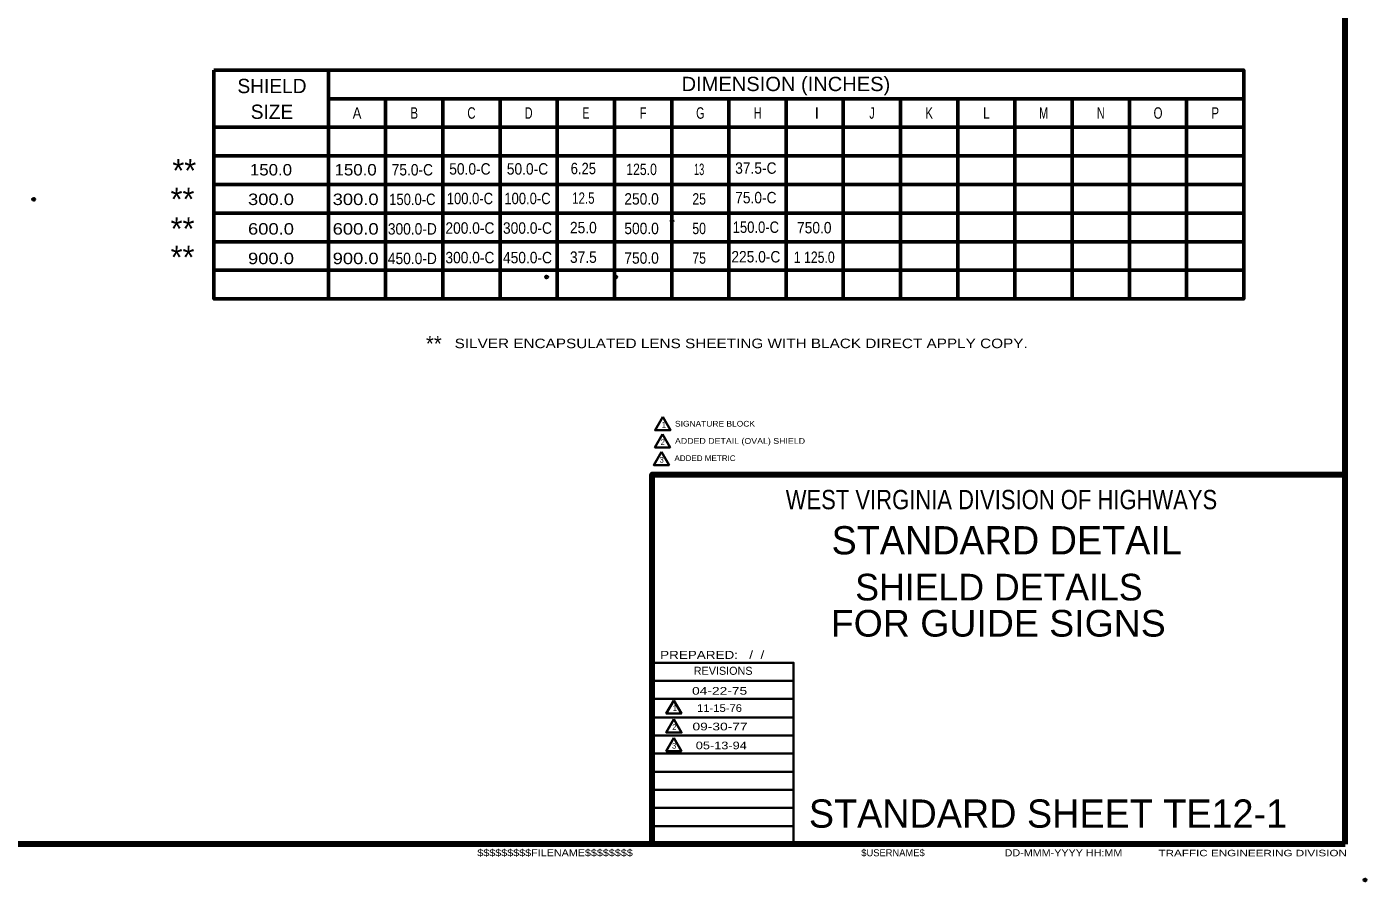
# Model space of a CAD drawing. Extents: x -96 to 760, y -448 to 96.
# Drawn here: x 338.4 to 759.8, y -448.1 to -179.2 of the extents above; entities that cross this region are included whole.
import ezdxf
from ezdxf.enums import TextEntityAlignment as Align

# ---------------------------------------------------------------- set-up
doc = ezdxf.new("R2010")
doc.units = 0
doc.header["$LTSCALE"] = 1.4
doc.header["$PDMODE"] = 32
doc.header["$PDSIZE"] = 0.7
doc.layers.add('1', color=7, linetype='Continuous', lineweight=40)
doc.layers.add('61', color=7, linetype='Continuous', lineweight=35)

msp = doc.modelspace()

# ---------------------------------------------------------------- linework, layer by layer
at = {"layer": '1', "lineweight": 158}
for q in [(753.127, 89.656), (753.127, -320.144), (-38.473, -436.444)]:
    msp.add_line((753.127, -436.444), q, dxfattribs=at)
at = {"layer": '1', "lineweight": 13}
msp.add_line((753.127, -436.444), (753.127, 89.656), dxfattribs=at)
at = {"layer": '1', "lineweight": 53}
for p, q in [((433.269, -264.853), (433.269, -192.853)), ((433.269, -201.853), (721.269, -201.853)), ((451.269, -264.853), (451.269, -201.853)), ((469.269, -264.853), (469.269, -201.853)), ((487.269, -264.853), (487.269, -201.853)), ((505.269, -264.853), (505.269, -201.853)), ((523.269, -264.853), (523.269, -201.853)), ((541.269, -264.853), (541.269, -201.853)), ((559.269, -264.853), (559.269, -201.853)), ((577.269, -264.853), (577.269, -201.853)), ((595.269, -264.853), (595.269, -201.853)), ((613.269, -264.853), (613.269, -201.853)), ((631.269, -264.853), (631.269, -201.853)), ((649.269, -264.853), (649.269, -201.853)), ((667.269, -264.853), (667.269, -201.853)), ((685.269, -264.853), (685.269, -201.853)), ((703.269, -264.853), (703.269, -201.853)), ((577.269, -210.853), (595.269, -210.853)), ((590.769, -210.853), (617.769, -210.853)), ((397.269, -219.853), (721.269, -219.853)), ((397.269, -228.853), (721.269, -228.853)), ((397.269, -237.854), (721.269, -237.854)), ((397.269, -246.854), (721.269, -246.854)), ((397.269, -255.854), (721.269, -255.854))]:
    msp.add_line(p, q, dxfattribs=at)
at = {"layer": '1', "lineweight": 35}
for p, q in [((579.627, -385.044), (535.127, -385.044)), ((579.627, -390.744), (535.127, -390.744)), ((579.627, -396.544), (535.127, -396.544)), ((579.627, -402.244), (535.127, -402.244)), ((579.627, -407.944), (535.127, -407.944)), ((579.627, -413.644), (535.127, -413.644)), ((579.627, -419.344), (535.127, -419.344)), ((579.627, -425.044), (535.127, -425.044)), ((579.627, -430.744), (535.127, -430.744))]:
    msp.add_line(p, q, dxfattribs=at)
at = {"layer": '1', "lineweight": 53}
msp.add_lwpolyline([(397.269, -192.853), (721.269, -192.853), (721.269, -264.853), (397.269, -264.853)], close=True, dxfattribs=at)
for points in [[(397.269, -210.853), (433.269, -210.853), (451.269, -210.853), (469.269, -210.853), (487.269, -210.853), (505.269, -210.853), (523.269, -210.853), (541.269, -210.853), (559.269, -210.853), (581.769, -210.853)], [(613.269, -210.853), (631.269, -210.853), (649.269, -210.853), (667.269, -210.853), (685.269, -210.853), (703.269, -210.853), (721.269, -210.853)]]:
    msp.add_lwpolyline(points, dxfattribs=at)
at = {"layer": '1', "lineweight": 35}
for points in [[(538.465, -302.008), (536.065, -306.165), (540.865, -306.165)], [(538.375, -307.418), (535.976, -311.575), (540.776, -311.575)], [(538.037, -313.012), (535.637, -317.169), (540.437, -317.169)], [(541.94, -391.203), (539.539, -395.359), (544.34, -395.359)], [(541.983, -397.144), (539.583, -401.3), (544.383, -401.3)], [(541.943, -402.987), (539.543, -407.144), (544.343, -407.144)]]:
    msp.add_lwpolyline(points, close=True, dxfattribs=at)
at = {"layer": '1', "lineweight": 158}
msp.add_lwpolyline([(535.127, -436.444), (535.127, -320.144), (753.127, -320.144)], dxfattribs=at)
at = {"layer": '1', "lineweight": 35}
msp.add_lwpolyline([(579.627, -436.444), (579.627, -379.344), (535.127, -379.344)], dxfattribs=at)
at = {"layer": '1'}
for p in [(340.552, -233.54), (541.41, -240.277), (501.934, -257.972), (523.715, -257.972), (759.427, -447.744)]:
    msp.add_point(p, dxfattribs=at)
at = {"layer": '61', "lineweight": 53}
for q in [(600.427, -436.444), (600.427, -436.444), (600.427, -436.444), (600.727, -436.444), (600.727, -436.444)]:
    msp.add_line((753.127, -436.444), q, dxfattribs=at)

# ---------------------------------------------------------------- texts
at = {"layer": '1'}
for s, height, p in [('SHIELD', 4.5, (415.526, -200.103)), ('SIZE', 4.5, (415.526, -208.203)), ('I', 3.6, (586.931, -208.154)), ('**', 7.2, (387.929, -228.069)), ('**', 7.2, (387.379, -237.064)), ('**', 7.2, (387.379, -246.365)), ('**', 7.2, (387.379, -255.334)), ('**', 4.8, (466.44, -281.338)), ('STANDARD DETAIL', 8.881, (646.677, -345.244)), ('SHIELD DETAILS', 8.391, (644.222, -359.745))]:
    msp.add_text(s, height=height, dxfattribs=at).set_placement(p, align=Align.CENTER)
for s, height, width, p in [('DIMENSION (INCHES)', 4.5, 1.05, (577.215, -199.456)), ('A', 3.6, 0.85, (442.283, -208.154)), ('B', 3.6, 0.75, (460.283, -208.154)), ('C', 3.6, 0.75, (478.283, -208.154)), ('D', 3.6, 0.7, (496.283, -208.154)), ('E', 3.6, 0.7, (514.283, -208.154)), ('F', 3.6, 0.75, (532.283, -208.154)), ('G', 3.6, 0.7, (550.283, -208.154)), ('H', 3.6, 0.7, (568.283, -208.154)), ('J', 3.6, 0.7, (604.283, -208.154)), ('K', 3.6, 0.75, (622.283, -208.154)), ('L', 3.6, 0.75, (640.283, -208.154)), ('M', 3.6, 0.7, (658.283, -208.154)), ('N', 3.6, 0.7, (676.283, -208.154)), ('O', 3.6, 0.75, (694.283, -208.154)), ('P', 3.6, 0.75, (712.283, -208.154)), ('150.0', 3.6, 1.1, (415.206, -226.014)), ('150.0', 3.6, 1.1, (441.839, -226.014)), ('75.0-C', 3.6, 0.9, (459.683, -226.014)), ('50.0-C', 3.6, 0.9, (477.794, -225.747)), ('50.0-C', 3.6, 0.9, (495.905, -225.747)), ('6.25', 3.6, 0.85, (513.483, -225.614)), ('125.0', 3.6, 0.8, (531.802, -225.879)), ('13', 3.6, 0.6, (549.913, -225.879)), ('37.5-C', 3.6, 0.9, (567.757, -225.48)), ('300.0', 3.6, 1.2, (415.206, -235.314)), ('300.0', 3.6, 1.2, (441.839, -235.314)), ('150.0-C', 3.6, 0.85, (459.683, -235.314)), ('100.0-C', 3.6, 0.85, (477.794, -235.047)), ('100.0-C', 3.6, 0.85, (495.905, -235.047)), ('12.5', 3.6, 0.75, (513.483, -234.914)), ('250.0', 3.6, 0.9, (531.802, -235.179)), ('25', 3.6, 0.8, (549.913, -235.179)), ('75.0-C', 3.6, 0.9, (567.757, -234.78)), ('600.0', 3.6, 1.2, (415.206, -244.614)), ('600.0', 3.6, 1.2, (441.839, -244.614)), ('300.0-D', 3.6, 0.9, (459.683, -244.614)), ('200.0-C', 3.6, 0.9, (477.794, -244.347)), ('300.0-C', 3.6, 0.9, (495.905, -244.347)), ('25.0', 3.6, 0.9, (513.483, -244.214)), ('500.0', 3.6, 0.9, (531.802, -244.479)), ('50', 3.6, 0.8, (549.913, -244.479)), ('150.0-C', 3.6, 0.85, (567.757, -244.08)), ('750.0', 3.6, 0.9, (586.134, -244.237)), ('900.0', 3.6, 1.2, (415.206, -253.914)), ('900.0', 3.6, 1.2, (441.839, -253.914)), ('450.0-D', 3.6, 0.9, (459.683, -253.914)), ('300.0-C', 3.6, 0.9, (477.794, -253.647)), ('450.0-C', 3.6, 0.9, (495.905, -253.647)), ('37.5', 3.6, 0.9, (513.483, -253.514)), ('750.0', 3.6, 0.9, (531.802, -253.779)), ('75', 3.6, 0.8, (549.913, -253.779)), ('225.0-C', 3.6, 0.9, (567.757, -253.38)), ('1 125.0', 3.6, 0.8, (586.134, -253.537)), ('WEST VIRGINIA DIVISION OF HIGHWAYS', 6.089, 0.85, (645.027, -331.044)), ('FOR GUIDE SIGNS', 8.391, 1.05, (644.022, -371.119)), ('04-22-75', 2.4, 1.35, (556.352, -389.393)), ('11-15-76', 2.4, 1.1, (556.328, -394.806)), ('09-30-77', 2.4, 1.35, (556.485, -400.618)), ('05-13-94', 2.4, 1.25, (556.883, -406.573))]:
    msp.add_text(s, height=height, dxfattribs=dict(at, width=width)).set_placement(p, align=Align.CENTER)
for s, height, width, p in [('SILVER ENCAPSULATED LENS SHEETING WITH BLACK DIRECT APPLY COPY.', 3, 1.2, (472.984, -280.35)), ('SIGNATURE BLOCK', 1.8, 1.1, (542.316, -305.031)), ('2', 1.8, 0.9, (537.821, -310.807)), ('ADDED DETAIL (OVAL) SHIELD', 1.8, 1.15, (542.316, -310.455)), ('3', 1.8, 0.9, (537.482, -316.401)), ('ADDED METRIC', 1.8, 1.05, (542.146, -315.879)), ('PREPARED:   /  /  ', 2.537, 1.25, (537.627, -378.144)), ('2', 1.8, 0.9, (541.428, -400.532)), ('3', 1.8, 0.9, (541.388, -406.376)), ('$$$$$$$$$FILENAME$$$$$$$$', 2.2, 1.15, (480.127, -440.244)), ('DD-MMM-YYYY HH:MM', 2.2, 1.15, (646.027, -440.244)), ('TRAFFIC ENGINEERING DIVISION', 2.031, 1.35, (694.427, -440.244))]:
    msp.add_text(s, height=height, dxfattribs=dict(at, width=width)).set_placement(p)
for s, height, p in [('1', 1.8, (538.128, -305.338)), ('REVISIONS', 2.537, (548.227, -383.144)), ('1', 1.8, (541.602, -394.532)), ('STANDARD SHEET TE12-1', 8.881, (584.427, -431.244)), ('$USERNAME$', 2.2, (600.927, -440.244))]:
    msp.add_text(s, height=height, dxfattribs=at).set_placement(p)

doc.saveas('drawing.dxf')
